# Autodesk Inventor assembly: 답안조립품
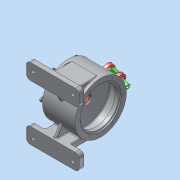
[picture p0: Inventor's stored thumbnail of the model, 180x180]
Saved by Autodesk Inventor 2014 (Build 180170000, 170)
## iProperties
Created: 2025-12
Part Number: 답안조립품
Document SubType Name: Assembly
Designer: dg
Author: dg
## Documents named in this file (13)
- C:\Users\dg\Desktop\751203V1010\답안조립품.iam
- C:\Users\dg\Desktop\751203V1010\본체.ipt
- C:\Users\dg\Desktop\751203V1010\가져온 구성요소\출력 축\출력 축.ipt
- C:\Users\dg\Desktop\751203V1010\가져온 구성요소\깊은 홈 볼 베어링 6005\깊은 홈 볼 베어링 6005.ipt
- C:\Users\dg\Desktop\751203V1010\가져온 구성요소\커버\커버.ipt
- C:\Users\dg\Desktop\751203V1010\가져온 구성요소\오일 실 25 40 8\오일 실 25 40 8.ipt
- C:\Users\dg\Desktop\751203V1010\가져온 구성요소\평행 키 6x6x16\평행 키 6x6x16.ipt
- C:\Users\dg\Desktop\751203V1010\가져온 구성요소\종동 기어\종동 기어.ipt
- C:\Users\dg\Desktop\751203V1010\가져온 구성요소\칼라 2\칼라 2.ipt
- C:\Users\dg\Desktop\751203V1010\가져온 구성요소\깊은 홈 볼 베어링 6004\깊은 홈 볼 베어링 6004.ipt
- C:\Users\dg\Desktop\751203V1010\가져온 구성요소\6각 머리 볼트 M8x20\6각 머리 볼트 M8x20.ipt
- C:\Users\dg\Desktop\751203V1010\가져온 구성요소\C형 멈춤링 구멍용 42\C형 멈춤링 구멍용 42.ipt
- C:\Users\dg\Desktop\751203V1010\가져온 구성요소\기어 축\기어 축.ipt
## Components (7 placed, 2 different names)
1. C형 멈춤링 구멍용 42:1
2. 6각 머리 볼트 M8x20:1
3. 6각 머리 볼트 M8x20:2
4. 6각 머리 볼트 M8x20:3
5. 6각 머리 볼트 M8x20:4
6. 6각 머리 볼트 M8x20:5
7. 6각 머리 볼트 M8x20:6
